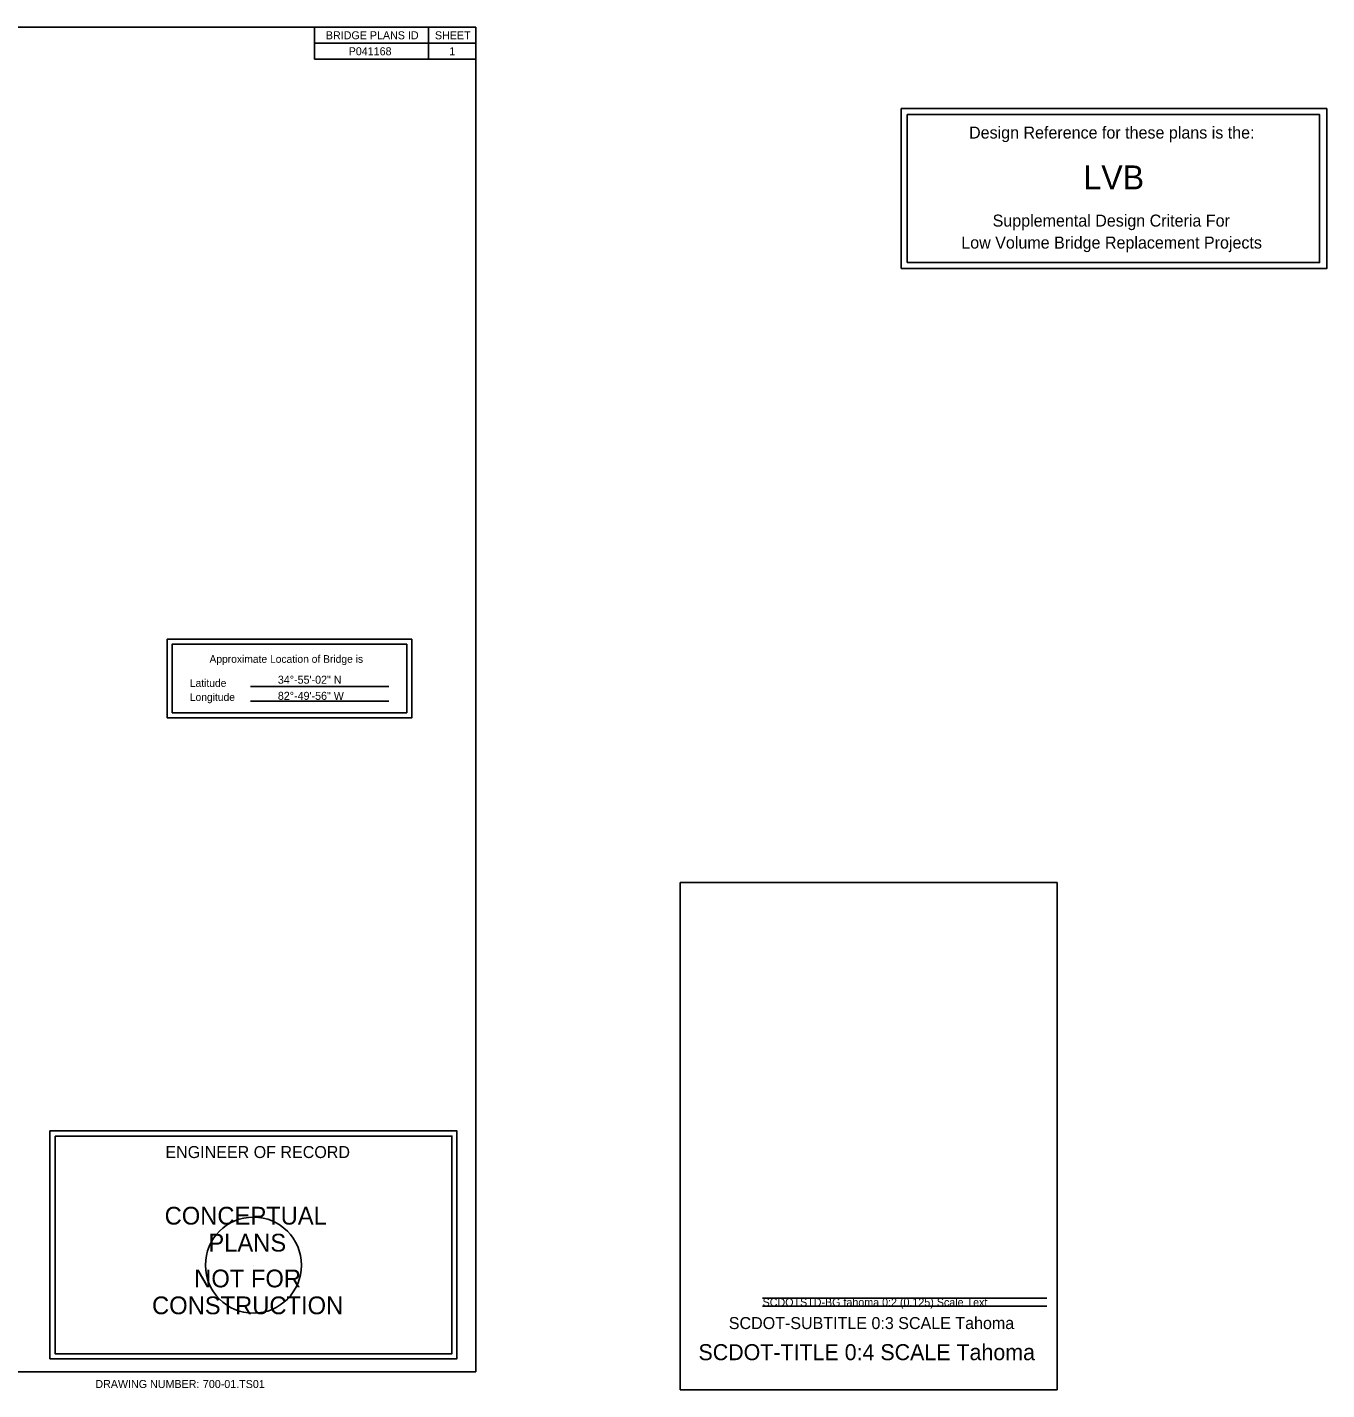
# Model space of a CAD drawing. Extents: x -2.9 to 3.9, y -2.5 to 1.79.
# Drawn here: x 2.208 to 3.9, y 0.018 to 1.792 of the extents above; entities that cross this region are included whole.
import ezdxf

# ---------------------------------------------------------------- set-up
doc = ezdxf.new("R2010")
doc.units = 0
for name, color, linetype in [('BR_AUTO DIMENSION', 7, 'Continuous'), ('BR_BORDER LINES', 7, 'Continuous'), ('BR_DETAILS', 7, 'Continuous'), ('BR_TEXT', 7, 'Continuous'), ('Default', 7, 'Continuous'), ('NoPlot', 7, 'Continuous')]:
    doc.layers.add(name, color=color, linetype=linetype)

msp = doc.modelspace()

# ---------------------------------------------------------------- linework, layer by layer
at = {"layer": 'BR_AUTO DIMENSION'}
for p, q in [((3.1651, 0.1373), (3.5352, 0.1373)), ((3.1651, 0.1269), (3.5352, 0.1269))]:
    msp.add_line(p, q, dxfattribs=at)
for points in [[(3.3457, 1.4775), (3.8996, 1.4775), (3.8996, 1.6859), (3.3457, 1.6859)], [(3.3535, 1.4854), (3.8902, 1.4854), (3.8902, 1.6781), (3.3535, 1.6781)], [(3.0579, 0.6784), (3.5485, 0.6784), (3.5485, 0.0182), (3.0579, 0.0182)]]:
    msp.add_lwpolyline(points, close=True, dxfattribs=at)
at = {"layer": 'BR_BORDER LINES'}
for p, q in [((2.5815, 1.7917), (2.5815, 1.75)), ((2.73, 1.7917), (2.73, 1.75)), ((2.7917, 1.7708), (2.5815, 1.7708)), ((2.7917, 1.75), (2.5815, 1.75))]:
    msp.add_line(p, q, dxfattribs=at)
msp.add_lwpolyline([(0.1667, 1.7917), (2.7917, 1.7917), (2.7917, 0.0417), (0.1667, 0.0417)], close=True, dxfattribs=at)
at = {"layer": 'BR_DETAILS'}
for p, q in [((2.4982, 0.9337), (2.6784, 0.9337)), ((2.4982, 0.9144), (2.6784, 0.9144))]:
    msp.add_line(p, q, dxfattribs=at)
for points in [[(2.7084, 0.9954), (2.39, 0.9954), (2.39, 0.8927), (2.7084, 0.8927)], [(2.7017, 0.9887), (2.3966, 0.9887), (2.3966, 0.8994), (2.7017, 0.8994)], [(2.2372, 0.3551), (2.7672, 0.3551), (2.7672, 0.0585), (2.2372, 0.0585)], [(2.2439, 0.3485), (2.7606, 0.3485), (2.7606, 0.0651), (2.2439, 0.0651)]]:
    msp.add_lwpolyline(points, close=True, dxfattribs=at)
at = {"layer": 'NoPlot'}
msp.add_line((2.5022, 0.1804), (2.5022, 0.1804), dxfattribs=at)
msp.add_circle((2.5022, 0.1804), 0.0625, dxfattribs=at)

# ---------------------------------------------------------------- texts
at = {"layer": 'BR_AUTO DIMENSION'}
for s, height, p in [('Design Reference for these plans is the:', 0.015625, (3.4339, 1.6468)), ('LVB', 0.03125, (3.5828, 1.5806)), ('Supplemental Design Criteria For', 0.015625, (3.4646, 1.5322)), ('Low Volume Bridge Replacement Projects', 0.015625, (3.4238, 1.5036)), ('34°-55\'-02" N', 0.010417, (2.534, 0.9372)), ('82°-49\'-56" W', 0.010417, (2.534, 0.9162)), ('SCDOTSTD-BG tahoma 0:2 (0.125) Scale Text', 0.010417, (3.1651, 0.1269))]:
    msp.add_text(s, height=height, dxfattribs=at).set_placement(p)
at = {"layer": 'BR_DETAILS'}
for s, p in [('Approximate Location of Bridge is', (2.445, 0.9644)), ('Latitude', (2.4194, 0.9331)), ('Longitude', (2.4194, 0.9148))]:
    msp.add_text(s, height=0.01, dxfattribs=at).set_placement(p)
for s, height, p in [('CONCEPTUAL', 0.02311, (2.3866, 0.2332)), ('PLANS', 0.02311, (2.4435, 0.1981)), ('NOT FOR', 0.02311, (2.4251, 0.1515)), ('CONSTRUCTION', 0.023108, (2.3702, 0.1165))]:
    msp.add_text(s, height=height, rotation=360, dxfattribs=at).set_placement(p)
at = {"layer": 'BR_TEXT'}
for s, height, p in [('SCDOT-SUBTITLE 0:3 SCALE Tahoma', 0.015625, (3.1211, 0.0972)), ('SCDOT-TITLE 0:4 SCALE Tahoma', 0.020833, (3.0816, 0.0567))]:
    msp.add_text(s, height=height, dxfattribs=at).set_placement(p)
at = {"layer": 'Default'}
for s, height, p in [('BRIDGE PLANS ID', 0.010417, (2.5965, 1.776)), ('SHEET', 0.01042, (2.7385, 1.776)), ('P041168', 0.01042, (2.6262, 1.7552)), ('1', 0.0104, (2.7572, 1.7552)), ('ENGINEER OF RECORD', 0.015625, (2.3876, 0.3198)), ('DRAWING NUMBER:', 0.010417, (2.2964, 0.0205)), ('700-01.TS01', 0.010417, (2.4364, 0.0205))]:
    msp.add_text(s, height=height, dxfattribs=at).set_placement(p)

doc.saveas('drawing.dxf')
